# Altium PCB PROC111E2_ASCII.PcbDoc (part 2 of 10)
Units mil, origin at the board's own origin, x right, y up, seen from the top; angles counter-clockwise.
Board outline 7700 x 2300 mil, 6 copper layers (Top Layer, GND 1, SIG 1, SIG 2, GND 2, Bottom Layer), stack 78.711 mil thick; 767 components, 596 nets, 2755 pads, 1578 vias.
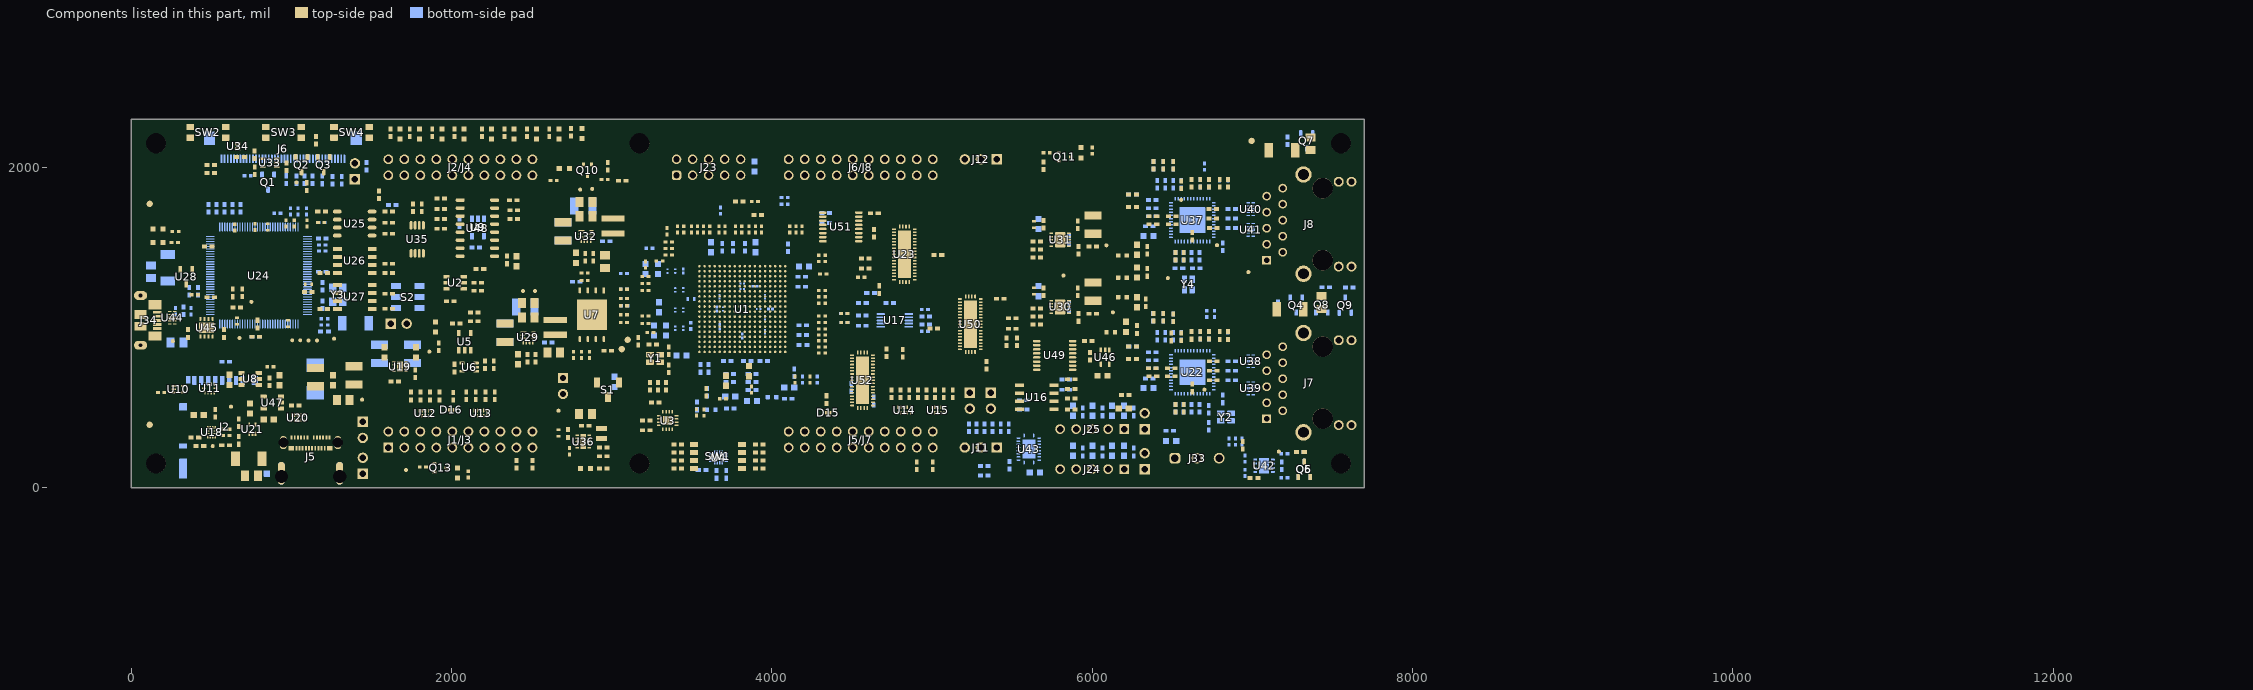
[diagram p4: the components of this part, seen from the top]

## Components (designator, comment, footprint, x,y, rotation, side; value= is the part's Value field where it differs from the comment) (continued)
C164 "GRM32ER7YA106KA12K" 1210_270 6004.13,1223.43 r90 top
C165 "GRM155R70J104KA01D" 0402 5909.13,1222.1 r90 top
C166 "GRM155R72A272KA01D" 0402 5854.25,1128.43 r90 bottom
C167 "GRM32ER7YA106KA12K" 1210_270 2332.33,966.68 r90 top
C168 "GRM32ER7YA106KA12K" 1210_270 2332.33,966.68 r90 bottom
C169 "GRM21BZ71A226ME15L" 0805_HV 2839,1694.3 r180 top
C170 "GRM21BZ71A226ME15L" 0805_HV 2839,1784.3 r180 top
C171 "GRM32ER71A476ME15L" 1210_270 2822.09,1759.3 r180 bottom
C172 "GRM188Z71C475KE21D" 0603 5664.13,1646.29 r90 bottom
C173 "GCM155C71A105KE38D" 0402_070 5635.58,1643.07 r90 top
C174 "GRM155R71E104KE14D" 0402 5695.21,1643.29 r90 top
C175 "GRM32ER7YA106KA12K" 1210_270 6004.13,1642.62 r90 top
C176 "GRM155R70J104KA01D" 0402 5909.13,1641.29 r90 top
C177 "GRM188R71E474KA12D" 0603 2774.51,1434.3 r270 top
C178 "GRM155R72A272KA01D" 0402 5854.25,1547.62 r90 bottom
C179 "GRM32ER7YA106KA12K" 1210_270 2694,1599.3 r90 bottom
C180 "GRM32ER7YA106KA12K" 1210_270 2694,1599.3 r90 top
C181 "GRM155R71E104KE14D" 0402 680.93,2065 r180 top
C182 "GRM155R71E104KE14D" 0402 769.3,1977.87 r90 top
C183 "GRM155R71E104KE14D" 0402 495.31,1965 r0 top
C184 "GRM155R71E104KE14D" 0402 494.74,2015 r0 top
C185 "GRM21BZ71A226ME15L" 0805_HV 2835,458.99 r180 top
C186 "GRM155R71E104KE14D" 0402 2835,385.96 r180 top
C187 "GCM155C71A105KE38D" 0402_070 2666.85,340.12 r90 top
C188 "GRM155R71E104KE14D" 0402 2726.93,337.66 r90 top
C189 "GRM1555C1E120JA01D" 0402 6541.38,1370 r180 bottom
C190 "GRM1555C1E120JA01D" 0402 6648.62,1370 r0 bottom
C191 "GRM188Z71A106MA73D" 0603 6279,1485.21 r90 top
C192 "GRM155R70J103KA01D" 0402 6344,1481.38 r90 top
C193 "GRM155R70J105MA12D" 0402 6556.28,1891.71 r90 top
C194 "GRM155R70J104KA01D" 0402 6556.28,1895.08 r90 bottom
C195 "GRM155R70J105MA12D" 0402 6498.94,1695.04 r0 top
C196 "GRM155R70J104KA01D" 0402 6379.14,1695.04 r180 top
C197 "GRM155R70J105MA12D" 0402 6751.41,1679.88 r180 top
C198 "GRM155R70J104KA01D" 0402 6870.21,1679.88 r0 bottom
C199 "GRM188Z71A106MA73D" 0603 6278.93,1156.97 r270 top
C200 "GRM155R70J103KA01D" 0402 6334,1154.99 r270 top
C201 "GRM155R70J105MA12D" 0402 6755.41,1620.83 r180 top
C202 "GRM155R70J104KA01D" 0402 6870.21,1620.83 r0 bottom
C203 "GRM155R70J105MA12D" 0402 6751.41,1738.94 r180 top
C204 "GRM155R70J104KA01D" 0402 6870.21,1738.94 r0 bottom
C205 "GRM188Z71A106MA73D" 0603 6351.36,1571.24 r180 bottom
C206 "GRM155R70J103KA01D" 0402 6355.51,1631.97 r180 bottom
C207 "GRM155R70J105MA12D" 0402 6625,1570.47 r90 top
C208 "GRM155R70J104KA01D" 0402 6670,1445 r270 bottom
C209 "GRM155R70J105MA12D" 0402 6498.94,1645.04 r0 top
C210 "GRM155R70J104KA01D" 0402 6379.14,1645.04 r180 top
C211 "GCM188R71H104KA57D" 0603 5880,230 r90 bottom
C212 "GCM188R71H104KA57D" 0603 5880,480 r90 bottom
C213 "GCM188R71H104KA57D" 0603 3890,2005 r270 bottom
C214 "GCM1885C1H102JA16D" 0603 6199.18,230 r90 bottom
C215 "GRM1885C1H101JA01D" 0603 6124.18,230 r90 bottom
C216 "GCM1885C1H102JA16D" 0603 6000,230 r90 bottom
C217 "GCM1885C1H102JA16D" 0603 6199.18,480 r90 bottom
C218 "GRM1885C1H101JA01D" 0603 6124.18,480 r90 bottom
C219 "GCM1885C1H102JA16D" 0603 6000,480 r90 bottom
C220 "GCM1885C1H102JA16D" 0603 6492.17,290.82 r0 bottom
C221 "GCM1885C1H102JA16D" 0603 6197.13,494.67 r180 top
C222 "GCM155R71H472KA37D" 0402 6940,265 r90 top
C223 "GRM155R71E104KE14D" 0402 5483.66,140.04 r90 bottom
C224 "GCM188R71H104KA57D" 0603 5642.05,93.47 r180 bottom
C225 "GRM155R71E104KE14D" 0402 7182.8,136.46 r270 bottom
C226 "GRM155R71E104KE14D" 0402 7010,60.4 r180 top
C227 "GRM21BZ71E106KE15L" 0805_HV 285,906.68 r0 bottom
C228 "GRM1555C1H150JA01D" 0402 658.65,1124.76 r180 top
C229 "GR442QR73D102KW01L" 1808 731.46,180.12 r0 top
C230 "GR442QR73D102KW01L" 1808 227.89,1373.06 r270 bottom
C231 "GRM155C81C225KE11D" 0402 352.83,962.27 r90 top
C232 "GCM155C71A105KE38D" 0402_070 660,1040.15 r90 top
C233 "GRM155R71E104KE14D" 0402 577.56,962.27 r270 top
C234 "GR442QR73D102KW01L" 1808 1398.86,1025 r0 bottom
C235 "GR442QR73D102KW01L" 1808 7235,1115 r0 top
C236 "C1608X7S1A335K080AC" 0603 2405.95,1413.5 r270 top
C237 "GRM155R70J104KA01D" 0402 2345.94,1421.38 r270 top
C238 "GRM155R71E104KE14D" 0402 5425,1178.69 r180 top
C239 "GRM155R71E104KE14D" 0402 5339.88,764.77 r90 top
C240 "GRM155R71E104KE14D" 0402 4670.38,1236.85 r90 top
C241 "GRM155R71E104KE14D" 0402 4636.65,1588.39 r90 top
C242 "GRM155R71E104KE14D" 0402 5036.38,1451.95 r180 top
C243 "GRM155R71E104KE14D" 0402 4495.23,625.31 r90 bottom
C244 "GRM155R71E104KE14D" 0402 4635,540.45 r270 bottom
C245 "GRM155R71E104KE14D" 0402 4715,841.18 r270 top
C246 "GRM155R71E104KE14D" 0402 4640,1712.48 r180 top
C247 "GR442QR73D102KW01L" 1808 7185.15,2106.97 r0 top
C248 "GCM188R71C104KA37J" 0603 6064.09,698.38 r180 top
C249 "GCM188R71C104KA37J" 0603 856.86,425.41 r0 top
D1 "SMBJ6.5CA" SMB-Bi 1147.56,678.07 r270 bottom
D2 "150060VS75000" WL-SMCW_GREEN 1898.27,1001.7 r270 top
D3 "150060VS75000" WL-SMCW_GREEN 165,1531.39 r0 top
D4 "150060VS75000" WL-SMCW_GREEN 2812.72,2212.24 r90 top
D5 "150060VS75000" WL-SMCW_GREEN 2036.27,91.9 r270 top
D6 "150060VS75000" WL-SMCW_GREEN 2835,119.75 r0 top
D7 "150060VS75000" WL-SMCW_GREEN 2669.29,2208.31 r90 top
D8 "150060VS75000" WL-SMCW_GREEN 2529.29,2208.31 r90 top
D9 "150060VS75000" WL-SMCW_GREEN 2389.29,2208.31 r90 top
D10 "150060VS75000" WL-SMCW_GREEN 2249.29,2208.31 r90 top
D11 "150060VS75000" WL-SMCW_GREEN 2077.87,2208.31 r90 top
D12 "150060VS75000" WL-SMCW_GREEN 1937.87,2208.31 r90 top
D13 "150060VS75000" WL-SMCW_GREEN 1797.87,2208.31 r90 top
D14 "150060VS75000" WL-SMCW_GREEN 1677.87,2208.31 r90 top
D15 "TPD1E01B04DPYR" DPY0002A 4351.58,466.66 r180 top
D16 "TPD1E01B04DPYR" DPY0002A 1997.72,485.1 r180 top
DS1 "150060RS75000" WL-SMCW_RED 2703,1992.4 r180 top
DS2 "150060RS75000" WL-SMCW_RED 5930.69,2090.86 r90 top
DS3 "150060RS75000" WL-SMCW_RED 165,1614.41 r0 top
FB1 "BLM18EG121SN1D" FP-BLM18EG121SN1D_0603-MFG 4000.08,564.71 r180 bottom
FB2 "BLM18EG121SN1D" FP-BLM18EG121SN1D_0603-MFG 3621.02,485 r180 bottom
FB3 "BLM18EG121SN1D" FP-BLM18EG121SN1D_0603-MFG 6188.68,1310.55 r0 top
FB4 "BLM18EG121SN1D" FP-BLM18EG121SN1D_0603-MFG 6115.92,970.9 r0 top
FB5 "BLM18EG121SN1D" FP-BLM18EG121SN1D_0603-MFG 6188.68,1449.44 r0 top
FB6 "BLM18EG121SN1D" FP-BLM18EG121SN1D_0603-MFG 6188.68,1188.64 r0 top
FID1 "Fiducial" Fiducial10-20 6995.38,2165 r90 top
FID2 "Fiducial" Fiducial10-20 113.79,392.07 r90 top
FID3 "Fiducial" Fiducial10-20 113.79,1771.83 r90 top
J1 "PBC02SAAN" Sullins_PBC02SAAN 1395.54,1975 r180 top locked
J1/J3 "SSQ-110-03-T-D" BoosterPack_40pin_J1J3 2054.17,300 r270 bottom locked
J2 "DM3BT-DSF-PEJS" Hirose_DM3BT-DSF-PEJS 570,362.52 r180 bottom locked
J2/J4 "SSQ-110-03-T-D" BoosterPack_40pin_J2J4 2054.17,2000 r270 bottom locked
J5 "2012670005" FP-2012670005_CONN_USB_9MM39_8MM21-MFG 1118.35,154.53 r0 top locked
J5/J7 "SSQ-110-03-T-D" BoosterPack_40pin_J5J7 4554.17,300 r270 bottom locked
J6 "FH12A-40S-0.5SH(55)" FP-FH12A-40S-0.5SH(55)_FFC40-MFG 945.63,2200 r180 bottom locked
J6/J8 "SSQ-110-03-T-D" BoosterPack_40pin_J6J8 4554.17,2000 r270 bottom locked
J7 "LPJG16314A4NL" FP-LPJG16314A4NL_CONN_RJ45-MFG 7444,655 r90 top locked
J8 "LPJG16314A4NL" FP-LPJG16314A4NL_CONN_RJ45-MFG 7444,1645 r90 top locked
J9 "PBC02SAAN" Sullins_PBC02SAAN 1445,136.05 r180 top
J10 "PBC02SAAN" Sullins_PBC02SAAN 1445,360 r0 top
J11 "PBC03SAAN" PBC03SAAN 5304.17,250 r180 top locked
J12 "PBC03SAAN" PBC03SAAN 5304.17,2050 r180 top locked
J13 "PBC02SAAN" Sullins_PBC02SAAN 5235.83,543.25 r0 top
J14 "PBC02SAAN" Sullins_PBC02SAAN 5367.11,543.25 r0 top
J15 "PBC02SAAN" Sullins_PBC02SAAN 6327.06,165 r180 top
J16 "PBC02SAAN" Sullins_PBC02SAAN 6327.06,415 r180 top
J17 "PBC02SAAN" Sullins_PBC02SAAN 1668.62,1023.77 r90 top
J18 "PBC02SAAN" Sullins_PBC02SAAN 2695,634.47 r0 top
J23 "PRPC005DAAN-RC" Sullins_xxPC005DAAN-RC 3604.17,2000 r90 top locked
J24 "PEC05SAAN" Sullins_PxC05SAAN 5999.18,115 r180 top locked
J25 "PEC05SAAN" Sullins_PxC05SAAN 5999.18,365 r180 top locked
J33 "OSTTE030161" On-Shore_OSTTE030161 6654.17,183.86 r0 top locked
J34 "1051640001" Molex_1051640001 0,1044.08 r270 top
L1 "BLM21PG300SH1D" 0805_HV 1322.44,547.65 r0 top
L2 "74438356022" WE-MAPI_4020 2645.75,1000.74 r90 top
L3 "74438356022" WE-MAPI_4020 3007.43,1633.36 r90 top
L4 "74405020100" FP-74405020100_SMT_IND_2MM0_1MM6-MFG 2935,338.84 r90 top
LBL1 "THT-14-423-10" Label_650x200 6610,2187.06 r0 top
Logo1 "CE Mark" CE_Mark_5mm 735,1417.13 r0 top
Logo2 "Texas Instruments" TI_Stacked_Overlay_Small 5135,1778.31 r0 top locked
Logo3 "FCC disclaimer" FCC_disclaimer 9836.36,4289 r270 bottom
Logo4 "WEEE logo" WEEE_Minimum 6005,838.02 r180 bottom
Q1 "IRLML6401TRPBF" SOT-23 852.98,1907.76 r270 bottom
Q2 "IRLML6401TRPBF" SOT-23 1062.25,2017.02 r270 top
Q3 "IRLML6401TRPBF" SOT-23 1201.12,2017.02 r270 top
Q4 "BSS123" SOT-23 7274.1,1140 r270 bottom
Q5 "BSS123" SOT-23 7324,113.66 r90 top
Q6 "BSS123" SOT-23 7324,113.66 r90 bottom
Q7 "BSS123" SOT-23 7340,2165 r270 bottom
Q8 "BSS123" SOT-23 7433.87,1140.67 r90 bottom
Q9 "BSS123" SOT-23 7580.33,1139.39 r90 bottom
Q10 "BSS223PWH6327" SOT-323 2848,1981 r270 top
Q11 "BSS123W-7-F" SOT-323 5828,2065.27 r0 top
Q13 "BSS123W-7-F" SOT-323 1930,123.39 r0 top
R1 "ERJ-2RKF1002X" 0402 3237.47,633.24 r270 top
R2 "CRCW04022K67FKED" 0402 3337.66,633.24 r90 top
R3 "ERJ-2GE0R00X" 0402L 3575.19,468.53 r90 top
R4 "ERJ-2GE0R00X" 0402L 3240.9,969.06 r180 top
R5 "ERJ-2GE0R00X" 0402 2048.11,1654.66 r270 bottom
R6 "ERJ-2RKF1002X" 0402 2162.72,1229.13 r180 top
R7 "ERJ-2GE0R00X" 0402L 3410,1612.48 r90 top
R8 "ERJ-2RKF1002X" 0402 3563.14,109.77 r0 bottom
R9 "ERJ-2GE0R00X" 0402L 3074.77,1238.11 r0 top
R10 "ERJ-2RKF1002X" 0402 3215,358.58 r0 top
R11 "ERJ-2RKF1002X" 0402 3270,530.76 r0 top
R12 "ERJ-2GE0R00X" 0402L 3074.77,1135.05 r0 top
R13 "ERJ-2GE0R00X" 0402L 3074.77,1181.64 r0 top
R14 "ERJ-2RKF1002X" 0402 3411.93,119.51 r0 top
R15 "ERJ-2RKF1002X" 0402 3411.93,169.51 r0 top
R16 "ERJ-2RKF1002X" 0402 3411.93,219.51 r0 top
R17 "ERJ-2RKF1002X" 0402 3411.93,269.51 r0 top
R18 "ERJ-2GE0R00X" 0402 2140.8,1039.07 r0 top
R19 "ERJ-2RKF49R9X" 0402 2262.84,767.39 r270 top
R20 "ERJ-2RKF1002X" 0402 2140.8,1094.07 r180 top
R21 "ERJ-2GEJ102X" 0402 1545,1829.63 r90 top
R22 "ERJ-2GEJ102X" 0402 3920,119.51 r180 top
R23 "ERJ-2GEJ102X" 0402 3920,169.51 r180 top
R24 "ERJ-2GEJ102X" 0402 3920,219.51 r180 top
R25 "ERJ-2GEJ102X" 0402 3920,269.51 r180 top
R26 "ERJ-2GE0R00X" 0402L 2810,828.96 r270 top
R27 "ERJ-2GE0R00X" 0402L 2760,828.96 r270 top
R28 "ERJ-2GE0R00X" 0402L 2830,1339.27 r180 top
R29 "ERJ-2GE0R00X" 0402L 2830,1293.54 r180 top
R30 "ERJ-2GE0R00X" 0402L 2860,828.96 r270 top
R31 "CRCW040247K5FKED" 0402 3255,893.53 r180 top
R32 "ERJ-6ENF1004V" 0805_HV 749.55,73.93 r180 top
R33 "ERJ-2GE0R00X" 0402L 3669,1612.48 r90 top
R34 "ERJ-2GE0R00X" 0402L 3573,1612.48 r90 top
R35 "ERJ-2GE0R00X" 0402L 3611,1612.48 r90 top
R36 "ERJ-2GE0R00X" 0402L 3535,1612.48 r90 top
R37 "ERJ-2GE0R00X" 0402L 3497,1612.48 r90 top
R38 "ERJ-2GE0R00X" 0402L 3449,1612.48 r90 top
R39 "CRCW040210K0FKED" 0402L 867.24,754.8 r180 top
R40 "CRCW040210K0FKED" 0402L 185,594.53 r180 top
R41 "CRCW040210K0FKED" 0402L 3678.01,1730 r90 bottom
R42 "ERJ-2RKF1002X" 0402 3164.53,914.8 r270 top
R43 "ERJ-2RKF1002X" 0402 2776.98,1285 r0 bottom
R44 "ERJ-2GE0R00X" 0402L 3872.63,611.52 r90 top
R45 "ERJ-2GE0R00X" 0402L 3528.72,469.92 r90 top
R46 "ERJ-2GE0R00X" 0402L 3344.16,1600.48 r270 top
R47 "ERJ-2GE0R00X" 0402L 3355,1534 r0 top
R48 "ERJ-2GE0R00X" 0402L 3234.69,1495 r0 bottom
R49 "ERJ-2GE0R00X" 0402L 3297.5,1415.5 r0 top
R50 "ERJ-2GE0R00X" 0402L 3355,1493.5 r0 top
R51 "ERJ-2GE0R00X" 0402L 3355,1453.5 r0 top
R52 "ERJ-2GE0R00X" 0402L 3210.5,1391.92 r270 top
R53 "ERJ-2GE0R00X" 0402L 3075,1336.34 r0 bottom
R54 "ERJ-2GE0R00X" 0402L 3209.68,1317.26 r0 top
R55 "CRCW04024K70JNED" 0402 2404.17,146.38 r270 top
R56 "CRCW04024K70JNED" 0402 2504.17,146.38 r270 top
R57 "ERJ-2GE0R00X" 0402L 3209.68,1274.26 r0 top
R58 "ERJ-2GE0R00X" 0402L 3209.68,1231.26 r0 top
R59 "ERJ-2GE0R00X" 0402L 3075,1181.51 r0 bottom
R60 "ERJ-2GE0R00X" 0402L 3077.77,1135.05 r0 bottom
R61 "ERJ-2GE0R00X" 0402L 4955.28,975.79 r0 bottom
R62 "ERJ-2GE0R00X" 0402L 4955.28,1111.7 r0 bottom
R63 "CRCW04024K70JNED" 0402 4959.21,1019.06 r0 bottom
R64 "CRCW04024K70JNED" 0402 4959.21,1068.43 r0 bottom
R65 "ERJ-2GE0R00X" 0402L 4312.25,840.82 r180 top
R66 "ERJ-2GE0R00X" 0402L 4312.25,878.82 r180 top
R67 "ERJ-2GE0R00X" 0402L 4312.25,916.82 r180 top
R68 "ERJ-2GE0R00X" 0402L 4312.25,952.82 r180 top
R69 "ERJ-2GE0R00X" 0402L 4312.25,1030.82 r180 top
R70 "ERJ-2GE0R00X" 0402L 4312.25,989.82 r180 top
R71 "ERJ-2GE0R00X" 0402L 4312.25,1071.65 r180 top
R72 "ERJ-2GE0R00X" 0402L 4451.61,1086.73 r180 top
R73 "CRCW04024K70JNED" 0402 4564.79,1010.55 r180 bottom
R74 "CRCW04024K70JNED" 0402 4564.79,1074.9 r180 bottom
R75 "ERJ-2GE0R00X" 0402L 4451.61,1029.87 r180 bottom
R76 "ERJ-2GE0R00X" 0402L 4452.24,1029.87 r180 top
R77 "ERJ-2GE0R00X" 0402L 4312.25,1191.33 r180 top
R78 "ERJ-2GE0R00X" 0402L 4557.16,1313.21 r180 top
R79 "ERJ-2GE0R00X" 0402L 4449.67,1086.88 r180 bottom
R80 "ERJ-2GE0R00X" 0402L 4312.25,1151.33 r180 top
R81 "ERJ-2GE0R00X" 0402L 4312.25,1450.76 r180 top
R82 "ERJ-2GE0R00X" 0402L 4187,1612.48 r270 top
R83 "ERJ-2GE0R00X" 0402L 4320,1333.3 r180 top
R84 "ERJ-2GE0R00X" 0402L 4312.25,1410.76 r180 top
R85 "ERJ-2GE0R00X" 0402L 4149,1612.48 r270 top
R86 "ERJ-2GE0R00X" 0402L 4111,1612.48 r270 top
R87 "ERJ-2GE0R00X" 0402L 4078.97,1769.24 r180 bottom
R88 "ERJ-2GE0R00X" 0402L 4078.97,1812.24 r180 bottom
R89 "ERJ-2GE0R00X" 0402L 592.82,324.31 r0 top
R90 "ERJ-2GE0R00X" 0402L 592.82,364.41 r0 top
R91 "CRCW0402200KJNED" 0402 587.51,263.69 r0 top
R92 "ERJ-2RKF1002X" 0402 669.95,404.69 r270 top
R93 "ERJ-2RKF1002X" 0402 669.95,294.31 r90 top
R94 "CRCW0402909KFKED" 0402 427.85,260.08 r180 top
R95 "CRCW04024K70JNED" 0402 396.4,312.6 r0 top
R96 "ERJ-2GEJ102X" 0402 5986.5,820 r270 top
R97 "ERJ-2GEJ102X" 0402 523.29,463.41 r270 top
R98 "ERJ-2RKF1002X" 0402 1645,663.27 r0 top
R99 "ERJ-2GE0R00X" 0402L 3074.77,1079.62 r0 top
R100 "ERJ-2GE0R00X" 0402 6375.51,745.04 r0 bottom
R101 "ERJ-2GE0R00X" 0402 6506.28,945 r270 bottom
R102 "ERJ-2GE0R00X" 0402 6375.51,795.04 r0 bottom
R103 "ERJ-2GE0R00X" 0402 6375.51,845.04 r0 bottom
R104 "ERJ-2GE0R00X" 0402 6406.28,945 r270 bottom
R105 "ERJ-2GE0R00X" 0402 6456.28,945 r270 bottom
R106 "ERJ-2GE0R00X" 0402 6493.31,940.44 r90 top
R107 "ERJ-2RKF1152X" 0402 6815,553.37 r90 bottom
R108 "CRCW04022K49FKED" 0402 6251.3,802.65 r180 top
R109 "CRCW04022K49FKED" 0402 6251.38,880.96 r180 top
R110 "CRCW04022K49FKED" 0402 6729.39,950.08 r90 top
R111 "CRCW04022K49FKED" 0402 6796.28,949.68 r90 top
R112 "CRCW04022K49FKED" 0402 6674.39,950.08 r90 top
R113 "CRCW04022K49FKED" 0402 6506.28,1059.68 r90 top
R114 "CRCW04022K49FKED" 0402 6520,495 r270 top
R115 "CRCW04022K49FKED" 0402 6383.01,1062.96 r90 top
R116 "CRCW04022K49FKED" 0402 6443.01,1062.97 r90 top
R117 "ERJ-2GE0R00X" 0402 6570,495 r90 bottom
R118 "ERJ-2GE0R00X" 0402 6520,495 r90 bottom
R119 "ERJ-2GE0R00X" 0402 6620,495 r90 bottom
R120 "CRCW04022K49FKED" 0402 6251.3,802.65 r0 bottom
R121 "CRCW04022K49FKED" 0402 6251.49,880.85 r0 bottom
R122 "CRCW04022K49FKED" 0402 6729.39,950.08 r270 bottom
R123 "CRCW04022K49FKED" 0402 6848,949.68 r270 top
R124 "CRCW04022K49FKED" 0402 6674.39,950.08 r270 bottom
R125 "CRCW04022K49FKED" 0402 6506.28,1059.68 r270 bottom
R126 "CRCW04022K49FKED" 0402 6570.85,495 r90 top
R127 "CRCW04022K49FKED" 0402 6379.14,1062.97 r270 bottom
R128 "CRCW04022K49FKED" 0402 6443.01,1062.97 r270 bottom
R129 "ERJ-2GE0R00X" 0402 480.5,1744.01 r270 bottom
R130 "ERJ-2GE0R00X" 0402L 1205.5,1054.21 r180 bottom
R131 "ERJ-2GE0R00X" 0402 530.5,1744.01 r270 bottom
R132 "ERJ-2GEJ101X" 0402L 1205.5,1014.22 r0 bottom
R133 "CRCW040233R2FKED" 0402 580.5,1744.01 r270 bottom
R134 "CRCW040233R2FKED" 0402 630.5,1744.01 r270 bottom
R135 "CRCW040233R2FKED" 0402 680.5,1744.01 r270 bottom
R136 "CRCW0402330KFKED" 0402L 275.17,1101.38 r90 bottom
R137 "CRCW0402330KFKED" 0402L 371.47,1101.38 r270 bottom
R138 "CRCW04021K00FKED" 0402L 1187.62,1656.39 r0 bottom
R139 "CRCW04021K00FKED" 0402L 1093.35,1724.68 r90 bottom
R140 "CRCW04021K00FKED" 0402L 1039.13,1724.68 r90 bottom
R141 "CRCW04021K00FKED" 0402L 992.24,1724.68 r90 bottom
R142 "CRCW040249R9FKED" 0402L 1191.36,1514.93 r0 bottom
R143 "CRCW040210K0FKED" 0402L 1191.36,1476.93 r0 bottom
R144 "CRCW04021K00FKED" 0402L 395.32,1204.12 r180 top
R145 "CRCW04024K87FKED" 0402L 911.79,1713.62 r0 bottom
R146 "ERJ-2RKF1002X" 0402 2602.33,906.68 r0 bottom
R147 "ERJ-2RKF1002X" 0402 5654.13,1117.63 r180 top
R148 "ERJ-6ENF1822V" 0805_HV 2637.33,844.68 r180 top
R149 "ERJ-2GE0R00X" 0402 5654.13,1017.63 r0 top
R150 "ERJ-2GE0R00X" 0402 5654.13,1067.63 r0 top
R151 "CRCW04023K57FKED" 0402 6004.13,1085.98 r0 top
R152 "CRCW04021K69FKED" 0402 5914.13,1062.36 r90 top
R153 "CRCW04022K49FKED" 0402 2522.33,806.68 r270 top
R154 "CRCW04024K99FKED" 0402 2472.33,806.68 r90 top
R155 "ERJ-2RKF1002X" 0402 5654.13,1536.82 r180 top
R156 "ERJ-2RKF1002X" 0402 2965.12,1537.88 r0 bottom
R157 "ERJ-2GE0R00X" 0402 5654.13,1436.82 r0 top
R158 "ERJ-2GE0R00X" 0402 5654.13,1486.82 r0 top
R159 "CRCW04021K87FKED" 0402 6004.13,1505.17 r0 top
R160 "ERJ-6ENF1822V" 0805_HV 2956.47,1410.85 r90 top
R161 "CRCW04024K99FKED" 0402 5914.13,1481.55 r90 top
R162 "CRCW040215K4FKED" 0402 2884,1439.3 r270 top
R163 "CRCW04024K99FKED" 0402 2834,1439.3 r90 top
R164 "ERJ-2GE0R00X" 0402L 3707,1612.48 r270 top
R165 "ERJ-2GE0R00X" 0402L 3492.19,1009.41 r90 bottom
R166 "ERJ-2GE0R00X" 0402L 3773,1612.48 r270 top
R167 "ERJ-2GE0R00X" 0402L 3209.68,1024.38 r0 top
R168 "ERJ-2GE0R00X" 0402L 3209.68,1072.38 r0 top
R169 "ERJ-2GE0R00X" 0402L 3935,1612.48 r270 top
R170 "ERJ-2GE0R00X" 0402L 3893.31,1786.65 r0 top
R171 "ERJ-2GE0R00X" 0402L 3897,1612.48 r270 top
R172 "ERJ-2GE0R00X" 0402L 3857,1612.48 r270 top
R173 "ERJ-2RKF1002X" 0402 3910.59,1702.62 r180 top
R174 "ERJ-2RKF1002X" 0402 3795.44,1786.65 r180 top
R175 "CRCW04024K70JNED" 0402 4903.31,136.03 r270 top
R176 "CRCW04024K70JNED" 0402 5004.17,136.03 r270 top
R177 "ERJ-2RKF1002X" 0402 966.87,1923.62 r270 bottom
R178 "ERJ-2RKF1002X" 0402 968.08,2004.52 r270 top
R179 "ERJ-2RKF1002X" 0402 769.09,2077.36 r90 top
R180 "ERJ-2GE0R00X" 0402L 725.69,1947.32 r180 bottom
R181 "ERJ-2RKF1002X" 0402 1151.5,2170 r90 top
R182 "ERJ-2RKF1002X" 0402 1255,1920 r90 bottom
R183 "ERJ-2RKF1002X" 0402 1627.39,1765 r180 bottom
R184 "ERJ-2RKF1002X" 0402 1094.86,1880 r90 top
R185 "ERJ-2RKF1002X" 0402 1190.9,1920.91 r90 bottom
R186 "ERJ-2RKF1002X" 0402 1129.84,1921.38 r90 bottom
R187 "ERJ-2RKF1002X" 0402 1079.84,1921.38 r90 bottom
R188 "ERJ-2RKF1002X" 0402 1029.84,1921.38 r90 bottom
R189 "CRCW04024K70JNED" 0402 1468,2007 r90 bottom
R190 "CRCW04024K70JNED" 0402 1813.28,1748.34 r90 top
R191 "CRCW04024K70JNED" 0402 1312.52,1920 r270 bottom
R192 "CRCW04024K70JNED" 0402 1758.28,1748.34 r90 top
R193 "ERJ-2GE0R00X" 0402L 2735,226.63 r270 top
R194 "ERJ-2RKF1002X" 0402 2945,250.25 r0 top
R195 "ERJ-2RKF1003X" 0402 2945,195.25 r0 top
R196 "ERJ-2GE0R00X" 0402 6375.51,1695.04 r0 bottom
R197 "ERJ-2GE0R00X" 0402 6506.28,1895 r270 bottom
R198 "ERJ-2GE0R00X" 0402 6375.51,1745.04 r0 bottom
R199 "ERJ-2GE0R00X" 0402 6375.51,1795.04 r0 bottom
R200 "ERJ-2GE0R00X" 0402 6406.28,1895 r270 bottom
R201 "ERJ-2GE0R00X" 0402 6456.28,1895 r270 bottom
R202 "ERJ-2RKF1152X" 0402 6815,1503.37 r90 bottom
R203 "CRCW04022K49FKED" 0402 6251.38,1752.65 r180 top
R204 "CRCW04022K49FKED" 0402 6251.38,1830.96 r180 top
R205 "CRCW04022K49FKED" 0402 6506.28,2013.05 r90 top
R206 "CRCW04022K49FKED" 0402 6796.28,1899.68 r90 top
R207 "CRCW04022K49FKED" 0402 6674.39,1900.08 r90 top
R208 "CRCW04022K49FKED" 0402 6729.39,1900.08 r90 top
R209 "CRCW04022K49FKED" 0402 6520,1445 r270 top
R210 "CRCW04022K49FKED" 0402 6383.01,2012.97 r90 top
R211 "CRCW04022K49FKED" 0402 6443.01,2012.97 r90 top
R212 "ERJ-2GE0R00X" 0402 6570,1445 r90 bottom
R213 "ERJ-2GE0R00X" 0402 6520,1445 r90 bottom
R214 "ERJ-2GE0R00X" 0402 6620,1445 r90 bottom
R215 "CRCW04022K49FKED" 0402 6251.3,1752.65 r0 bottom
R216 "CRCW04022K49FKED" 0402 6251.38,1830.96 r0 bottom
R217 "CRCW04022K49FKED" 0402 6506.28,2013.05 r270 bottom
R218 "CRCW04022K49FKED" 0402 6848,1899.68 r270 top
R219 "CRCW04022K49FKED" 0402 6674.39,1900.08 r270 bottom
R220 "CRCW04022K49FKED" 0402 6729.39,1900.08 r270 bottom
R221 "CRCW04022K49FKED" 0402 6570.97,1444.88 r90 top
R222 "CRCW04022K49FKED" 0402 6383.01,2012.97 r270 bottom
R223 "CRCW04022K49FKED" 0402 6443.01,2012.97 r270 bottom
R224 "CRCW0402220RJNED" 0402 7160.2,1135 r270 bottom
R225 "ERJ-2GE0R00X" 0402L 6715,1084.62 r270 bottom
R226 "CRCW0402220RJNED" 0402 7300.38,221.46 r180 top
R227 "ERJ-2GE0R00X" 0402L 6762.73,1085 r270 bottom
R228 "CRCW0402220RJNED" 0402 7300.38,221.46 r180 bottom
R229 "ERJ-2GE0R00X" 0402L 6846.59,947.67 r270 bottom
R230 "CRCW0402220RJNED" 0402 7220,2165 r270 bottom
R231 "ERJ-2GE0R00X" 0402L 6700,2004.69 r270 bottom
R232 "CRCW0402220RJNED" 0402 7457.49,1251.28 r0 bottom
R233 "ERJ-2GE0R00X" 0402L 6795,1896.38 r270 bottom
R234 "CRCW0402220RJNED" 0402 7603.95,1250 r0 bottom
R235 "ERJ-2GE0R00X" 0402L 6848,1896.38 r270 bottom
R236 "ERJ-2RKF4992X" 0402 6259.18,222.12 r90 bottom
R237 "ERJ-2RKF4992X" 0402 6064.18,222.13 r90 bottom
R238 "ERJ-2RKF4992X" 0402 5940,222.13 r90 bottom
R239 "ERJ-2RKF4992X" 0402 6259.18,472.12 r90 bottom
R240 "ERJ-2RKF4992X" 0402 6064.18,472.13 r90 bottom
R241 "ERJ-2RKF4992X" 0402 5940,472.13 r90 bottom
R242 "ERJ-2RKF4992X" 0402 6485.13,355.53 r0 bottom
R243 "ERJ-2RKF4992X" 0402 6205,578.2 r180 top
R244 "CRCW040210K0FKED" 0402L 6935,287.55 r90 bottom
R245 "ERJ-2GE0R00X" 0402L 7200,211.46 r180 bottom
R246 "CRCW040261R9FKED" 0402L 6952.8,91.77 r90 bottom
R247 "CRCW040261R9FKED" 0402L 6952.8,181.14 r270 bottom
R248 "ERJ-2GE0R00X" 0402L 6855,287.55 r90 bottom
R249 "ERJ-2GE0R00X" 0402L 7200,61.46 r180 bottom
R250 "CRCW040210K0FKED" 0402L 6895,287.55 r270 bottom
R251 "CRCW040251K1FKED" 0402 631.97,1215.23 r90 top
R252 "CRCW040230K0FKED" 0402 691.97,1217.17 r270 top
R253 "ERJ-6ENF1004V" 0805_HV 122.89,1348.06 r90 bottom
R254 "ERJ-6ENF1004V" 0805_HV 7430.57,1155 r90 top
R255 "ERJ-6ENF1004V" 0805_HV 7364.16,2146.97 r90 top
R256 "ERJ-2GEJ102X" 0402 4816.77,838.02 r90 top
R257 "ERJ-2RKF5100X" 0402 1918.27,879.01 r270 top
R258 "ERJ-2RKF1002X" 0402 2974.53,2005.57 r90 top
R259 "ERJ-2GEJ361X" 0402L 270,1530 r0 top
R260 "ERJ-2GEJ361X" 0402L 275,1600 r0 top
R261 "CRCW04021K00FKED" 0402L 965,1650 r270 top
R262 "ERJ-2RKF2200X" 0402 2609.29,2216.18 r270 top
R263 "ERJ-2RKF2200X" 0402 2469.29,2216.18 r270 top
R264 "ERJ-2RKF2200X" 0402 2329.29,2216.18 r270 top
R265 "ERJ-2GEJ361X" 0402L 2636.09,1917.12 r180 top
R266 "ERJ-2RKF2200X" 0402 2189.29,2216.18 r270 top
R267 "ERJ-2RKF2200X" 0402 2017.87,2216.18 r270 top
R268 "ERJ-2RKF1002X" 0402 3065,1915.46 r0 top
R269 "ERJ-2RKF1002X" 0402 2388.01,1731.55 r180 top
R270 "ERJ-2RKF1002X" 0402 1930.93,1676.88 r0 top
R271 "ERJ-2RKF1002X" 0402 1930.93,1804.54 r0 top
R272 "ERJ-2GEJ511X" 0402L 2955,1923.35 r180 top
R273 "ERJ-2RKF2200X" 0402 1877.87,2216.18 r270 top
R274 "ERJ-2RKF1002X" 0402 1930.93,1739.85 r0 top
R275 "ERJ-2RKF1002X" 0402 2388.01,1676.55 r180 top
R276 "ERJ-2RKF1002X" 0402 1930.93,1616.57 r0 top
R277 "ERJ-2RKF2200X" 0402 1737.87,2216.18 r270 top
R278 "ERJ-2GEJ102X" 0402 2385,1795 r180 top
R279 "ERJ-2RKF2200X" 0402 1617.87,2216.18 r270 top
R280 "ERJ-2GE0R00X" 0402L 3074.77,1031.94 r0 top
R281 "ERJ-2GE0R00X" 0402L 3075,1239.6 r0 bottom
R282 "ERJ-2GE0R00X" 0402L 4143,674.68 r90 top
R283 "ERJ-2GE0R00X" 0402L 4190,674.68 r90 bottom
R284 "ERJ-2GE0R00X" 0402L 4282.93,674.68 r90 bottom
R285 "ERJ-2GE0R00X" 0402L 4236.47,674.68 r90 top
R286 "ERJ-2GE0R00X" 0402L 4312.25,1231.79 r180 top
R287 "ERJ-2RKF1002X" 0402 5530,911.55 r90 top
R288 "ERJ-2RKF1002X" 0402 4581.73,1430.9 r0 top
R289 "ERJ-2GEJ102X" 0402 5465.31,911.55 r90 top
R290 "ERJ-2GEJ102X" 0402 4581.73,1367.93 r0 top
R291 "ERJ-2RKF1002X" 0402 4565,1152.36 r0 bottom
R292 "ERJ-2RKF1002X" 0402 5501.38,1057.02 r180 top
R293 "ERJ-2GEJ102X" 0402 4615.26,1215.33 r180 bottom
R294 "ERJ-2GEJ102X" 0402 5501.38,992.02 r180 top
R295 "ERJ-2RKF1002X" 0402 1990,1163.59 r0 top
R296 "ERJ-2RKF1002X" 0402 2176.41,1365 r0 top
R297 "ERJ-2GE0R00X" 0402L 3811,1612.92 r270 top
R298 "ERJ-2RKF1002X" 0402 4336.51,1715.49 r180 bottom
R299 "ERJ-2RKF1002X" 0402 1023.5,512.5 r0 top
R300 "ERJ-2GEJ102X" 0402 4336.51,1652.52 r180 bottom
R302 "ERJ-2GEJ361X" 0402L 6000,2104.27 r270 top
R303 "ERJ-2GEJ511X" 0402L 5715,2090.86 r0 top
R304 "ERJ-2GEJ102X" 0402 5695.31,2008.64 r90 top
R305 "ERJ-2RKF1002X" 0402 6620,950 r270 top
R306 "ERJ-2RKF1002X" 0402 6620,1900.08 r270 top
R307 "ERJ-2GE0R00X" 0402L 3693.94,555 r0 top
R308 "CRCW04021K00FKED" 0402L 1016.99,1650 r270 top
R309 "CRCW04021K00FKED" 0402L 1095.89,1650 r270 top
R310 "CRCW04021K00FKED" 0402L 1184.6,1656.39 r0 top
R311 "CRCW04021K00FKED" 0402L 645,1625 r270 top
R312 "CRCW04021K00FKED" 0402L 772.07,1627.63 r270 top
R313 "CRCW0402130RFKED" 0402 2745.47,2220.12 r270 top
R314 "ERJ-2GEJ361X" 0402L 2103.52,81.9 r90 top
R315 "CRCW0402130RFKED" 0402 2945,120 r0 top
R316 "ERJ-2RKF1002X" 0402 5570,545.04 r0 bottom
R317 "ERJ-2GEJ511X" 0402L 1819.99,127.49 r0 top
R318 "ERJ-2RKF1002X" 0402 5868.93,488.21 r180 top
R319 "ERJ-2RKF1002X" 0402 5835.31,675 r180 bottom
R320 "ERJ-2RKF1002X" 0402 5868.93,676.73 r180 top
R321 "ERJ-2RKF1002X" 0402 5868.93,556.99 r180 top
R322 "ERJ-2RKF1002X" 0402 5835.31,611.02 r180 bottom
R323 "ERJ-2RKF1002X" 0402 5868.93,615 r180 top
R324 "CRCW040233R2FKED" 0402 1607.87,1653.35 r180 top
R325 "CRCW040233R2FKED" 0402 1607.87,1584.92 r180 top
R326 "CRCW040233R2FKED" 0402 1607.87,1398.01 r180 top
R327 "CRCW040233R2FKED" 0402 1607.87,1210 r180 top
R328 "CRCW040233R2FKED" 0402 5325,75 r0 bottom
R329 "CRCW040233R2FKED" 0402 5325,135.09 r0 bottom
R330 "CRCW040233R2FKED" 0402 5229.44,373.51 r270 bottom
R331 "CRCW040233R2FKED" 0402 5277.45,373.51 r270 bottom
R332 "CRCW040233R2FKED" 0402 5327.45,373.51 r270 bottom
R333 "CRCW040233R2FKED" 0402 5377.45,373.51 r270 bottom
R334 "CRCW040233R2FKED" 0402 5428.06,373.51 r270 bottom
R335 "CRCW040233R2FKED" 0402 5478.01,373.51 r270 bottom
S1 "CAS-120TA" SW_CAS-120TA 2975.61,610.94 r270 top
S2 "CAS-D20TA" SW_CAS-D20TA 1724.71,1190 r180 bottom
SH-J1 "60900213421" Wurth_60900213421 12985,2675 r90 top
SH-J2 "60900213421" Wurth_60900213421 9590,2508.18 r90 top
SH-J3 "60900213421" Wurth_60900213421 9590,2146.97 r90 top
SH-J4 "60900213421" Wurth_60900213421 1850.31,-280 r180 top
SH-J5 "60900213421" Wurth_60900213421 1875,-160 r180 top
SH-J6 "60900213421" Wurth_60900213421 4355,-120 r180 top
SH-J7 "60900213421" Wurth_60900213421 4345,-250 r180 top
SW1 "416131160804" FP-416131160804_SMT_SW-MFG 3662.3,194.51 r90 top
SW2 "434351045816" FP-434351045816_SMT_SW_4MM7_4MM5-MFG 477.56,2218.82 r180 top
SW3 "434351045816" FP-434351045816_SMT_SW_4MM7_4MM5-MFG 950,2218.82 r180 top
SW4 "434351045816" FP-434351045816_SMT_SW_4MM7_4MM5-MFG 1375,2218.82 r180 top
TP1 "TP_SM_1MM" TP_SM_1MM 3098.87,922.75 r90 top
TP2 "TP_SM_1MM" TP_SM_1MM 3061.79,864.43 r90 top
TP3 "TESTPOINT" TP_25MIL-SMT 621.55,505.45 r90 top
TP4 "TESTPOINT" TP_25MIL-SMT 1440,548.85 r180 top
TP5 "TESTPOINT" TP_25MIL-SMT 507.51,259.31 r90 top
TP6 "TESTPOINT" TP_25MIL-SMT 2666.85,480 r90 top
TP7 "TESTPOINT" TP_25MIL-SMT 6700.57,611.5 r180 top
TP8 "TESTPOINT" TP_25MIL-SMT 1860,848.96 r90 top
TP9 "TESTPOINT" TP_25MIL-SMT 2877.25,1865 r90 top
TP10 "TESTPOINT" TP_25MIL-SMT 2520,1228.07 r90 top
TP11 "TESTPOINT" TP_25MIL-SMT 6088.14,1513.04 r90 top
TP12 "TESTPOINT" TP_25MIL-SMT 6128.41,1094.72 r90 top
TP13 "TESTPOINT" TP_25MIL-SMT 1715,110 r90 top
TP14 "TESTPOINT" TP_25MIL-SMT 2802.41,1860.51 r90 top
TP15 "TESTPOINT" TP_25MIL-SMT 2445,1228.07 r90 top
TP16 "TESTPOINT" TP_25MIL-SMT 6471.65,1308.13 r90 top
TP17 "TESTPOINT" TP_25MIL-SMT 5820,1323.71 r90 top
TP18 "TESTPOINT" TP_25MIL-SMT 1030,1905 r90 top
TP19 "TESTPOINT" TP_25MIL-SMT 6779.03,1513.91 r0 top
TP20 "TESTPOINT" TP_25MIL-SMT 6555,1797.09 r270 top
TP21 "TESTPOINT" TP_25MIL-SMT 6975,1345.45 r90 top
TP22 "TESTPOINT" TP_25MIL-SMT 7165,225 r90 top
TP23 "TESTPOINT" TP_25MIL-SMT 258.56,915 r0 top
TP24 "TESTPOINT" TP_25MIL-SMT 748.48,1160.35 r0 top
TP25 "TESTPOINT" TP_25MIL-SMT 674.75,934.53 r270 top
TP26 "TESTPOINT" TP_25MIL-SMT 1265,929.89 r0 top
TP27 "TESTPOINT" TP_25MIL-SMT 1003.9,920 r270 top
TP28 "TESTPOINT" TP_25MIL-SMT 1053.9,920 r270 top
TP29 "TESTPOINT" TP_25MIL-SMT 1105.9,919 r270 top
TP30 "TESTPOINT" TP_25MIL-SMT 1158.9,919 r270 top
U1 "AM263x_0p96" "ZCZ (S-PBGA-N324)" 3547.13,1382.8 r0 top locked
U2 "SN74LVC1G11DBVR" DBV0006A_N 2021.24,1279.45 r0 top
U3 "TCA6408ARGTR" RGT0016A 3348.05,418.7 r90 top
U4 "SN74AVC4T245RSVR" RSV0016A 3666.07,187.78 r90 bottom
U5 "SN74LVC1G08DBVR" DBV0005A_N 2081.31,911.4 r90 top
U6 "SN74LVC1G17DCKR" DCK0005A_N 2108.67,752.39 r180 top
U7 "S25FL128SAGNFI000" FP-S25FL128SAGNFI000_WSON8-IPC_B 2875,1079.5 r270 top locked
U8 "TPS22918TDBVTQ1" DBV0006A_N 741.03,678.6 r180 top
U9 "SN74LVC1G08DBVR" DBV0005A_N 2163.97,1624.3 r270 bottom
U10 "TPD2E001DRLR" DRL0005A 292.78,614.21 r0 top
U11 "TPD6E001RSER" RSE0010A 488.2,620 r270 top
U12 "TPD4E02B04DQAR" DQA0010A#1 1835,464.48 r90 top
U13 "TPD4E02B04DQAR" DQA0010A#1 2180,465 r90 top
U14 "TPD4E02B04DQAR" DQA0010A#1 4825,484.12 r90 top
U15 "TPD4E02B04DQAR" DQA0010A#1 5035.4,484.26 r90 top
U16 "CAT24M01WI-GT3" SOIC-8 5652.8,564.14 r180 top
U17 "TS5A23159DGSR" DGS0010A_N 4767.68,1043.75 r0 bottom
U18 "TUSB320LIRWBR" RWB0012A 500.2,345.08 r0 top
U19 "TPS22965TDSGRQ1" DSG0008B 1676.92,755.91 r0 top
U20 "TPD4E02B04DQAR" DQA0010A#1 1038.54,436.99 r270 top
U21 "SN74AHC1G02DRLR" DRL0005A 755.3,365 r90 top
U22 "DP83869HMRGZT" RGZ0048B-MFG 6625.18,720.04 r180 bottom
U23 "TS3DDR3812RUAR" RUA0042A-MFG 4827.2,1456.5 r0 top
U24 "TM4C1294NCPDTT3" PDT0128A 795.5,1324.37 r0 bottom locked
U25 "ISO7220CDR" D0008B_N 1393.86,1648.86 r0 top
U26 "ISO7721DR" D0008B_HV 1395,1415 r180 top
U27 "ISO7721DR" D0008B_HV 1395,1190.27 r180 top
U28 "LM4040C25QDBZR" DBZ0003A_N 341.5,1316.65 r270 top
U29 "TPS62913RPUR" RPU0010A-MFG 2475.89,941.68 r180 top
U30 "TPS74801DRCR" DRC0010J 5799.13,1128.43 r0 top
U31 "TPS74801DRCR" DRC0010J 5799.13,1547.62 r0 top
U32 "TPS62913RPUR" RPU0010A-MFG 2837.56,1574.3 r180 top
U33 "SN74LVC1G07DCKT" DCK0005A_N 863.37,2028.15 r180 top
U34 "SN74LVC2G17DSF2" DSF0006A 665,2131.22 r270 top
U35 "TCA9617BDGKR" DGK0008A_N 1784.37,1550 r90 top
U36 "TPS62177DQCR" DQC0010A 2821.22,287.66 r0 top
U37 "DP83869HMRGZT" RGZ0048B-MFG 6625.18,1670.04 r180 bottom
U38 "TPD4E05U06DQAR" DQA0010A#2 6989.58,788.94 r180 bottom
U39 "TPD4E05U06DQAR" DQA0010A#2 6989.31,619.6 r180 bottom
U40 "TPD4E05U06DQAR" DQA0010A#2 6989.58,1738.94 r180 bottom
U41 "TPD4E05U06DQAR" DQA0010A#2 6989.31,1609.6 r180 bottom
U42 "TCAN1044VDRBTQ1" DRB0008J 7072.8,136.46 r180 bottom
U43 "TXB0108RGYR" RGY0020A 5603.66,240.62 r0 bottom
U44 "TPD4E02B04DQAR" DQA0010A#1 255,1060.81 r180 top
U45 "TPS79601DRBR" DRB0008B 468.69,998.32 r90 top
U46 "SN74LVC1G04DCKR" DCK0005A_N 6080,815 r270 top
U47 "SN74LVC1G08DBVR" DBV0005A_N 879.5,531 r180 top
U48 "TPIC2810D" D0016A_N 2160,1620 r180 top locked
U49 "SN74CB3Q3257PWR" PW0016A_L 5765,825.23 r0 top
U50 "TS3DDR3812RUAR" RUA0042A-MFG 5238.39,1020.04 r180 top
U51 "SN74CB3Q3257PWR" PW0016A_L 4430,1627.91 r0 top
U52 "TS3DDR3812RUAR" RUA0042A-MFG 4565,670 r180 top
Y1 "ABM10W-25.0000MHZ-4-D1X-T3" Abracon_ABM10W 3270,806.21 r90 top
Y2 "ABM10W-25.0000MHZ-4-D1X-T3" Abracon_ABM10W 6834.6,440.5 r90 bottom
Y3 "NX3225GA-16.000M-STD-CRG-1" NDK_NX3225GA 1287.13,1204.32 r180 bottom
Y4 "ABM10W-25.0000MHZ-4-D1X-T3" Abracon_ABM10W 6600,1268.41 r0 bottom
ZZ1 "This Assembly Note is for PCB labels only" AssemblyNoteLabel 100,7500 r0 top
ZZ2 "These assemblies are ESD sensitive, ESD precautions shall be observed." AssemblyNote 100,7400 r0 top
ZZ3 "These assemblies must be clean and free from flux and all contaminants. Use of no clean flux is not acceptable." AssemblyNote 100,7300 r0 top
ZZ4 "These assemblies must comply with workmanship standards IPC-A-610 Class 2, unless otherwise specified." AssemblyNote 100,7200 r0 top
? "Comment" MISTRAL_LOGO_25 6689.32,1155.04 r0 top
? "Comment" MHNP_M3_PANHEAD_PHILLIPS 3173.18,150 r0 top
? "Comment" MHNP_M3_PANHEAD_PHILLIPS 7554.17,150 r0 top
? "Comment" MHNP_M3_PANHEAD_PHILLIPS 7554.17,2150 r0 top locked
? "Comment" MHNP_M3_PANHEAD_PHILLIPS 3173.18,2150 r0 top locked
? "Comment" MHNP_M3_PANHEAD_PHILLIPS 154.17,2150 r0 top
? "Comment" MHNP_M3_PANHEAD_PHILLIPS 154.17,150 r0 top locked

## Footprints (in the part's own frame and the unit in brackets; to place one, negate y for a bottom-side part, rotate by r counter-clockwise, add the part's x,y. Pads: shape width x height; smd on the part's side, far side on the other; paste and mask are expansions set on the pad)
0201 [mm] "Data from Kemet datasheet CC101_COM dated 7/28/11"
  rect 0.46x0.42 smd mask+0: 1(-0.33,0) 2(0.33,0)
0402 [mm] "0402 from SM-752 data"
  rect 0.8x0.6 smd: 1(-0.6,0) 2(0.6,0)
  silkscreen extent -1.22,-0.52 1.22,0.52
0402_070 [mil] "SMD, 2-Leads, Body 1.2x0.7mm, Height 0.7mm"
  rect 15x24 smd: 1(-20,0) 2(20,0)
0402L [mm] "0402 from SM-752 data"
  rect 0.6x0.5 smd: 1(-0.5,0) 2(0.5,0)
0402S [mil] "Based on C0402S footprint from PADS legacy"
  rect 15x24 smd: 1(-20,0) 2(20,0)
0603 [mm] "0603 from SM-752 data"
  rect 1x0.95 smd: 1(-0.8,0) 2(0.8,0)
  silkscreen extent -1.52,-0.69 1.52,0.69
0805_HV [mil] "0805 with 30mil clearance between pads"
  rect 50x63 smd: 1(-40,0) 2(40,0)
  silkscreen extent -74,-40 74,40
1210_270 [mm] "1210"
  rect 1.3x2.7 smd: 1(-1.45,0) 2(1.45,0)
  silkscreen extent -2.32,-1.57 2.32,1.57
1808 [mm] "Chip Capacitor, Body 4.6x2.0mm, IPC Medium Density"
  rect 1.4x2.3 smd: 1(-2.1,0) 2(2.1,0)
  silkscreen extent -3.1,-1.45 3.1,1.45
Abracon_ABM10W [mm] "SMD, 4-Leads, Body 2x2.5mm"
  rrect12% 0.85x1.2 smd: 1(-0.6,0.813) 2(-0.6,-0.813) 3(0.6,-0.813) 4(0.6,0.813)
AssemblyNote [mil] "Assembly Note"
AssemblyNoteLabel [mil] "Assembly Note for PCB Labels"
BoosterPack_40pin_J1J3 [mm] "Receptacle, 2.54mm, 10x2, TH"
  rrect6% 1.55x1.55 hole 1.02: 1(1.27,11.43)
  round 1.55 hole 1.02: 2(1.27,8.89) 3(1.27,6.35) 4(1.27,3.81) 5(1.27,1.27) 6(1.27,-1.27) 7(1.27,-3.81) 8(1.27,-6.35) 9(1.27,-8.89) 10(1.27,-11.43) 21(-1.27,11.43) 22(-1.27,8.89) 23(-1.27,6.35) 24(-1.27,3.81) 25(-1.27,1.27) 26(-1.27,-1.27) 27(-1.27,-3.81) 28(-1.27,-6.35) 29(-1.27,-8.89) 30(-1.27,-11.43)
  silkscreen extent -7.62,-12.95 7.62,12.95
BoosterPack_40pin_J2J4 [mm] "Receptacle, 2.54mm, 10x2, TH"
  round 1.55 hole 1.02: 11(-1.27,-11.43) 12(-1.27,-8.89) 13(-1.27,-6.35) 14(-1.27,-3.81) 15(-1.27,-1.27) 16(-1.27,1.27) 17(-1.27,3.81) 18(-1.27,6.35) 19(-1.27,8.89) 20(-1.27,11.43) 31(1.27,-11.43) 32(1.27,-8.89) 33(1.27,-6.35) 34(1.27,-3.81) 35(1.27,-1.27) 36(1.27,1.27) 37(1.27,3.81) 38(1.27,6.35) 39(1.27,8.89) 40(1.27,11.43)
  silkscreen extent -7.62,-12.95 2.48,12.95
BoosterPack_40pin_J5J7 [mm] "Receptacle, 2.54mm, 10x2, TH"
  round 1.55 hole 1.02: 41(1.27,11.43) 42(1.27,8.89) 43(1.27,6.35) 44(1.27,3.81) 45(1.27,1.27) 46(1.27,-1.27) 47(1.27,-3.81) 48(1.27,-6.35) 49(1.27,-8.89) 50(1.27,-11.43) 61(-1.27,11.43) 62(-1.27,8.89) 63(-1.27,6.35) 64(-1.27,3.81) 65(-1.27,1.27) 66(-1.27,-1.27) 67(-1.27,-3.81) 68(-1.27,-6.35) 69(-1.27,-8.89) 70(-1.27,-11.43)
  silkscreen extent -2.48,-12.95 7.62,12.95
BoosterPack_40pin_J6J8 [mm] "Receptacle, 2.54mm, 10x2, TH"
  round 1.55 hole 1.02: 51(-1.27,-11.43) 52(-1.27,-8.89) 53(-1.27,-6.35) 54(-1.27,-3.81) 55(-1.27,-1.27) 56(-1.27,1.27) 57(-1.27,3.81) 58(-1.27,6.35) 59(-1.27,8.89) 60(-1.27,11.43) 71(1.27,-11.43) 72(1.27,-8.89) 73(1.27,-6.35) 74(1.27,-3.81) 75(1.27,-1.27) 76(1.27,1.27) 77(1.27,3.81) 78(1.27,6.35) 79(1.27,8.89) 80(1.27,11.43)
  silkscreen extent -7.62,-12.95 2.48,12.95
CE_Mark_5mm [mil] "Minimum text height for CE Mark"
D0008B_HV [mm] "SOIC, 8-Leads, Body 4.9x3.9mm, Pitch 1.27mm, HV / Isolation option"
  rrect17% 1.4x0.6 smd: 1(-2.75,1.905) 2(-2.75,0.635) 3(-2.75,-0.635) 4(-2.75,-1.905) 5(2.75,-1.905) 6(2.75,-0.635) 7(2.75,0.635) 8(2.75,1.905)
  silkscreen extent -3.3,-2.5 0.9,2.5
D0008B_N [mil] "SOIC, 8-Leads, Body 4.9x3.9mm, Pitch 1.27mm, IPC Medium Density"
  oval 55x23.62 smd: 1(-108.5,75) 2(-108.5,25) 3(-108.5,-25) 4(-108.5,-75) 5(108.5,-75) 6(108.5,-25) 7(108.5,25) 8(108.5,75)
  silkscreen extent -130,-98 35,98
D0016A_N [mm] "SOIC, 16-Leads, Body 9.9x3.9mm, Pitch 1.27mm, IPC Medium Density"
  oval 1.45x0.6 smd: 1(-2.725,4.445) 2(-2.725,3.175) 3(-2.725,1.905) 4(-2.725,0.635) 5(-2.725,-0.635) 6(-2.725,-1.905) 7(-2.725,-3.175) 8(-2.725,-4.445) 9(2.725,-4.445) 10(2.725,-3.175) 11(2.725,-1.905) 12(2.725,-0.635) 13(2.725,0.635) 14(2.725,1.905) 15(2.725,3.175) 16(2.725,4.445)
  silkscreen extent -3.3,-5 0.9,5
DBV0005A_N [mm] "SOT23, 5-Leads, Body 2.9x1.6mm, Pitch 0.95mm, Lead Span 2.8mm, IPC Medium Density"
  rrect17% 1x0.6 smd: 1(-1.375,0.95) 2(-1.375,0) 3(-1.375,-0.95) 4(1.375,-0.95) 5(1.375,0.95)
  silkscreen extent -0.25,-1.55 0.25,1.55
DBV0006A_N [mm] "SOT23, 6-Leads, Body 2.9x1.6mm, Pitch 0.95mm, Lead Span 2.8mm, IPC Medium Density"
  rrect17% 1x0.6 smd: 1(-1.375,0.95) 2(-1.375,0) 3(-1.375,-0.95) 4(1.375,-0.95) 5(1.375,0) 6(1.375,0.95)
  silkscreen extent -1.68,-1.55 0.5,1.55
DBZ0003A_N [mm] "SOT23, 3-Leads, Body 2.9x1.3mm, Pitch 0.95mm, Lead Span 2.4mm, IPC Medium Density"
  rrect17% 1x0.6 smd: 1(-1.2,0.95) 2(-1.2,-0.95) 3(1.2,0)
  silkscreen extent 0.2,-1.5 0.7,1.5
DCK0005A_N [mm] "SOT353, 5-Leads, Body 2x1.3mm, Pitch 0.65mm, Lead Span 2.1mm, IPC Medium Density"
  rrect25% 0.85x0.4 smd: 1(-1.125,0.65) 2(-1.125,0) 3(-1.125,-0.65) 4(1.125,-0.65) 5(1.125,0.65)
  silkscreen extent -1.48,-1.02 0.55,1.1
DGK0008A_N [mm] "TSOP, 8-Leads, Body 3x3mm, Pitch 0.65mm, IPC Medium Density"
  oval 1.35x0.45 smd: 1(-2.225,0.975) 2(-2.225,0.325) 3(-2.225,-0.325) 4(-2.225,-0.975) 5(2.225,-0.975) 6(2.225,-0.325) 7(2.225,0.325) 8(2.225,0.975)
  silkscreen extent -2.75,-1.55 0.95,1.55
DGS0010A_N [mm] "TSSOP, 10-Leads, Body 3x3mm, Pitch 0.5mm, IPC Medium Density"
  oval 1.35x0.3 smd: 1(-2.225,1) 2(-2.225,0.5) 3(-2.225,0) 4(-2.225,-0.5) 5(-2.225,-1) 6(2.225,-1) 7(2.225,-0.5) 8(2.225,0) 9(2.225,0.5) 10(2.225,1)
  silkscreen extent -2.75,-1.55 0.9,1.55
DPY0002A [mm] "X1SON-2"
  rrect57% 0.35x0.6 smd paste-0.5 mask+0: 1(-0.325,0) 2(0.325,0)
  rrect50% 0.3x0.5 on Top Paste: 1S(-0.35,0) 2S(0.35,0)
  silkscreen extent -0.85,-0.02 -0.8,0.02
DQA0010A#1 [mm] "SON, 10-Leads, Body 1x2.5mm, Pitch 0.5mm, TI Recommended"
  rrect50% 0.565x0.2 smd: 1(-0.417,1) 2(-0.417,0.5) 4(-0.417,-0.5) 5(-0.417,-1) 6(0.417,-1) 7(0.417,-0.5) 9(0.417,0.5) 10(0.417,1)
  rrect28% 0.565x0.36 on Top Paste: 3(-0.417,0) 8(0.417,0)
  rrect25% 0.565x0.4 smd paste-0.2: 3(-0.417,0) 8(0.417,0)
  silkscreen extent -0.67,-1.45 0.55,1.45
DQA0010A#2 [mm] "SON, 10-Leads, Body 1x2.5mm, Pitch 0.5mm, TI Recommended"
  rrect50% 0.565x0.2 smd: 1(-0.417,1) 2(-0.417,0.5) 4(-0.417,-0.5) 5(-0.417,-1) 6(0.417,-1) 7(0.417,-0.5) 9(0.417,0.5) 10(0.417,1)
  rrect28% 0.565x0.36 on Bottom Paste: 3(-0.417,0) 8(0.417,0)
  rrect25% 0.565x0.4 smd paste-0.2: 3(-0.417,0) 8(0.417,0)
  silkscreen extent -0.67,-1.45 0.55,1.45
DQC0010A [mm] "SON, 10-Leads, Body 2x3mm, Pitch 0.5mm, Thermal Pad 2.4x0.84mm"
  rrect40% 0.5x0.25 smd: 1(-0.95,1) 2(-0.95,0.5) 3(-0.95,0) 4(-0.95,-0.5) 5(-0.95,-1) 6(0.95,-1) 7(0.95,-0.5) 8(0.95,0) 9(0.95,0.5) 10(0.95,1)
  rrect12% 0.8x1.08 on Top Paste: 11(0,-0.64) 11(0,0.64)
  rrect12% 0.84x2.4 smd paste-0.42: 11(0,0)
  silkscreen extent -1.18,-1.68 1.17,1.68
DRB0008B [mm] "SON, 8-Leads, Body 3x3mm, Pitch 0.65mm, Thermal Pad 2.4x1.65mm, TI Recommended"
  rrect33% 0.6x0.3 smd: 1(-1.4,0.975) 2(-1.4,0.325) 3(-1.4,-0.325) 4(-1.4,-0.975) 5(1.4,-0.975) 6(1.4,-0.325) 7(1.4,0.325) 8(1.4,0.975)
  rrect50% 1.47x1.06 on Top Paste: 9(0,0.63) 9(0,-0.63)
  rrect6% 1.65x2.4 smd paste-1.2: 9(0,0)
  silkscreen extent -1.73,-1.73 1.73,1.73
DRB0008J [mm] "VSON-8"
  rrect33% 0.6x0.31 smd: 1(-1.4,0.975) 2(-1.4,0.325) 3(-1.4,-0.325) 4(-1.4,-0.975) 5(1.4,-0.975) 6(1.4,-0.325) 7(1.4,0.325) 8(1.4,0.975)
  rrect6% 1.65x2.4 smd paste-1.2: 9(0,0)
  silkscreen extent -1.73,-1.73 1.73,1.73
DRC0010J [mm] "VSON-10"
  rrect42% 0.6x0.24 smd: 1(-1.4,1) 2(-1.4,0.5) 3(-1.4,0) 4(-1.4,-0.5) 5(-1.4,-1) 6(1.4,-1) 7(1.4,-0.5) 8(1.4,0) 9(1.4,0.5) 10(1.4,1)
  rrect12% 1.65x2.4 smd paste-1 mask+0: 11(0,0)
DRL0005A [mm] "SOTFL, 5-Flat Leads, Body 1.2x1.6x0.6mm, Pitch 0.5mm, TI recommended"
  rrect33% 0.67x0.3 smd: 1(-0.74,0.5) 2(-0.74,0) 3(-0.74,-0.5) 4(0.74,-0.5) 5(0.74,0.5)
  silkscreen extent -0.9,-0.95 0.5,0.95
DSF0006A [mm] "TI recommended land pattern"
  rrect59% 0.6x0.17 smd mask+0: 1(-0.4,0.35) 2(-0.4,0) 3(-0.4,-0.35) 4(0.4,-0.35) 5(0.4,0) 6(0.4,0.35)
  silkscreen extent -0.6,-0.63 0.6,0.63
DSG0008B [mm] "SON, 8-Leads, Body 2x2mm, Pitch 0.5mm, Thermal Pad 1.6x0.9mm, TI Recommended"
  rrect14% 0.9x0.7 on Top Paste: 0(0,-0.45) 0(0,0.45)
  rrect40% 0.5x0.25 smd: 1(-0.95,0.75) 2(-0.95,0.25) 3(-0.95,-0.25) 4(-0.95,-0.75) 5(0.95,-0.75) 6(0.95,-0.25) 7(0.95,0.25) 8(0.95,0.75)
  rrect11% 0.9x1.6 smd paste-0.45: 9(0,0)
  silkscreen extent -1.07,-1.15 1.07,1.15
FCC_disclaimer [mil]
Fiducial10-20 [mm]
  round 1 smd mask+0: 1(0,0)
  Top Layer keep-out circle w1.178: c0,0 r0.5
FP-2012670005_CONN_USB_9MM39_8MM21-MFG [mm]
  rrect100% 1.1x2.1 hole 1.6 slot 0.6 at 0 deg paste-1000 mask+0: 1(-4.32,3.205) 2(4.32,3.205)
  rrect100% 0.6x2.1 hole 2.1 slot 0.6 at 0 deg paste-1000 mask+0: 3(-4.62,-2.155) 4(4.62,-2.155)
  rrect100% 1.1x3.6 smd paste-1000 mask+0: 3(-4.62,-1.655) 4(4.62,-1.655)
  rrect100% 1.1x3.6 smd far side paste-1000 mask+0: 3(-4.62,-1.655) 4(4.62,-1.655)
  rrect33% 0.3x0.7 smd paste+0 mask+0: A1(-3,4.015) A2(-2.5,4.015) A3(-2,4.015) A4(-1.5,4.015) A5(-1,4.015) A6(-0.5,4.015) A7(0.5,4.015) A8(1,4.015) A9(1.5,4.015) A10(2,4.015) A11(2.5,4.015) A12(3,4.015) B2(2.25,2.315) B3(1.75,2.315) B4(1.25,2.315) B5(0.75,2.315) B6(0.25,2.315) B7(-0.25,2.315) B8(-0.75,2.315) B9(-1.25,2.315) B10(-1.75,2.315) B11(-2.25,2.315)
  rrect14% 0.9x0.7 smd paste+0 mask+0: B1(3.05,2.315) B12(-3.05,2.315)
  silkscreen extent -4.77,0.52 4.77,5.03
FP-74405020100_SMT_IND_2MM0_1MM6-MFG [mm]
  rect 0.8x1.7 smd paste+0 mask+0: 1(-0.8,0) 2(0.8,0)
FP-416131160804_SMT_SW-MFG [mm]
  rrect13% 0.76x1.27 smd paste+0 mask+0: 1(-1.905,-3.81) 2(-0.635,-3.81) 3(0.635,-3.81) 4(1.905,-3.81) 5(1.905,3.81) 6(0.635,3.81) 7(-0.635,3.81) 8(-1.905,3.81)
  silkscreen extent -3.27,-4.12 3.27,2.93
FP-434351045816_SMT_SW_4MM7_4MM5-MFG [mm]
  rrect10% 1.2x1 smd paste+0 mask+0: 1(2.8,0.85) 2(2.8,-0.85) 3(-2.8,0.85) 4(-2.8,-0.85)
  silkscreen extent -2.4,0.73 4.07,1.85
FP-BLM18EG121SN1D_0603-MFG [mm]
  rrect15% 0.65x0.7 smd paste+0 mask+0: 1(-0.675,0) 2(0.675,0)
  silkscreen extent -0.87,-0.8 0.87,0.8
FP-FH12A-40S-0.5SH(55)_FFC40-MFG [mm]
  rrect33% 0.3x1.3 smd paste-1000 mask+0: 1(9.75,-3.725) 2(9.25,-3.725) 3(8.75,-3.725) 4(8.25,-3.725) 5(7.75,-3.725) 6(7.25,-3.725) 7(6.75,-3.725) 8(6.25,-3.725) 9(5.75,-3.725) 10(5.25,-3.725) 11(4.75,-3.725) 12(4.25,-3.725) 13(3.75,-3.725) 14(3.25,-3.725) 15(2.75,-3.725) 16(2.25,-3.725) 17(1.75,-3.725) 18(1.25,-3.725) 19(0.75,-3.725) 20(0.25,-3.725) 21(-0.25,-3.725) 22(-0.75,-3.725) 23(-1.25,-3.725) 24(-1.75,-3.725) 25(-2.25,-3.725) 26(-2.75,-3.725) 27(-3.25,-3.725) 28(-3.75,-3.725) 29(-4.25,-3.725) 30(-4.75,-3.725) 31(-5.25,-3.725) 32(-5.75,-3.725) 33(-6.25,-3.725) 34(-6.75,-3.725) 35(-7.25,-3.725) 36(-7.75,-3.725) 37(-8.25,-3.725) 38(-8.75,-3.725) 39(-9.25,-3.725) 40(-9.75,-3.725)
  rrect6% 1.8x2.2 smd paste+0 mask+0: 41(-11.65,-0.475) 42(11.65,-0.475)
  silkscreen extent -12.35,-5.07 12.35,3.2
FP-GRM033C80J105ME05D_0201-MFG [mm]
  rrect33% 0.3x0.35 smd paste+0 mask+0: 1(-0.282,0) 2(0.282,0)
  silkscreen extent -0.35,-0.58 0.35,0.58
FP-LPJG16314A4NL_CONN_RJ45-MFG [mm]
  rrect7% 1.4x1.4 hole 0.9 paste-1000 mask+0: 1(-5.715,9.015)
  round 1.4 hole 0.9 paste-1000 mask+0: 2(-4.445,6.475) 3(-3.175,9.015) 4(-1.905,6.475) 5(-0.635,9.015) 6(0.635,6.475) 7(1.905,9.015) 8(3.175,6.475) 9(4.445,9.015) 10(5.715,6.475)
  round 1.57 hole 1.02 paste-1000 mask+0: 11(6.725,-2.415) 12(6.725,-4.445) 13(-6.725,-2.415) 14(-6.725,-4.445)
  round 2.6 hole 1.7 paste-1000 mask+0: 15(-7.875,3.175) 16(7.875,3.175)
  round 3.25 hole 3.25 unplated paste-1000 mask+0: ""(-5.715,0.125) ""(5.715,0.125)
  silkscreen extent -9.65,-10.75 8.1,10.75
FP-S25FL128SAGNFI000_WSON8-IPC_B [mm]
  rrect25% 0.961x0.392 smd paste+0 mask+0: 1(-3.876,1.905)
  rrect100% 0.961x0.392 smd paste+0 mask+0: 2(-3.876,0.635) 3(-3.876,-0.635) 4(-3.876,-1.905) 5(3.876,-1.905) 6(3.876,-0.635) 7(3.876,0.635) 8(3.876,1.905)
  rrect2% 4.9x4.75 smd paste-1000 mask+0: 9(0,0)
  silkscreen extent -5.03,-3 4,3
Hirose_DM3BT-DSF-PEJS [mm] "Conncetor, micro SD, 8+2 Pos, R/A, SMT"
  rrect14% 0.7x1.4 smd: 1(-3.2,7.8) 2(-2.1,7.8) 3(-1,7.8) 4(0.1,7.8) 5(1.2,7.8) 6(2.3,7.8) 7(3.4,7.8) 8(4.5,7.8)
  rrect8% 1.2x0.8 smd: 9(6.3,-2.6)
  rrect14% 0.7x1.2 smd: 10(5.45,7.9)
  rrect10% 1x1.4 smd: S1(-5.1,7.8)
  rrect8% 1.2x1.2 smd: S2(6.3,3.6)
  rrect8% 1.2x3.2 smd: S3(6.3,-6.2)
  rrect8% 1x1 smd: S4(-7,-7)
Label_650x200 [mil] "Thermal Transfer Label"
  round 1 on Mech13: 0(0,0)
  silkscreen extent -325,-100 325,100
MHNP_M3_PANHEAD_PHILLIPS [mil]
  round 121 hole 126 unplated mask+0: ""(0,0)
  Keep-Out Layer circle w1: c0,0 r126
MISTRAL_LOGO_25 [mil]
  silkscreen extent 0,0 297,162
Molex_1051640001 [mm] "Receptacle, USB 2.0, Micro B, 5 Pos, 0.65mm Pitch, R/A, SMT"
  rrect22% 0.45x1.38 smd: 1(1.3,4.11) 2(0.65,4.11) 3(0,4.11) 4(-0.65,4.11) 5(-1.3,4.11)
  rrect7% 1.475x2.1 smd: 6(-2.462,3.75) 11(2.462,3.75)
  rrect100% 1.4x2.1 hole 0.6 slot 1.3 at 90 deg: 7(-3.95,1.45) 10(3.95,1.45)
  rrect7% 1.375x1.9 smd: 8(-0.937,1.45) 9(0.937,1.45)
  silkscreen extent 1.2,5.1 1.4,5.4
NDK_NX3225GA [mm] "NDK"
  rect 1.2x1.4 smd: 1(-0.8,1.1) 2(-0.8,-1.1) 3(0.8,-1.1) 4(0.8,1.1)
  silkscreen extent -1.9,-0.1 1.4,2
On-Shore_OSTTE030161 [mm] "Terminal Block, 3.5mm, 3x1, TH"
  rrect50% 1.7x1.7 hole 1.2: 1(-3.5,0)
  round 1.7 hole 1.2: 2(0,0) 3(3.5,0)
  silkscreen extent -5.25,-3.6 5.25,4.05
PBC03SAAN [mm] "Sullins 100mil, 1x3, 230 mil above insulator"
  rect 1.65x1.65 hole 1.016: 1(-2.54,0)
  round 1.65 hole 1.016: 2(0,0) 3(2.54,0)
  silkscreen extent -3.81,-1.27 3.81,1.27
